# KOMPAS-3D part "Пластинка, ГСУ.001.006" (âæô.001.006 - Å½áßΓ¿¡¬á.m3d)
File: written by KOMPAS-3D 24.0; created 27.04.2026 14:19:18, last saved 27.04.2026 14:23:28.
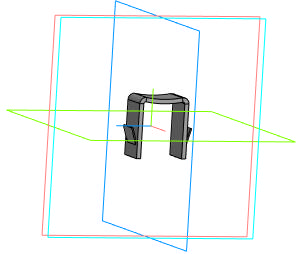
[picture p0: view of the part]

Document properties: Автор: User7; Полное имя файла: C:\Users\User7\Desktop\Двигатель мясорубки\ГСУ.001.006 - Пластинка.m3d

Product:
- Part/product: Пластинка  | designation ГСУ.001.006
    Масса: 0.002129

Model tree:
1. Эскиз:1
2. Обечайка:1
     Расстояние 1 = 7; Радиус сгиба = 0.4; Радиус сгиба = 0.4; Коэффициент = 0.4; Величина сгиба = 10; Радиус сгиба = 25.25; Коэффициент = 0.4; Величина сгиба = 10; Радиус сгиба = 0.4; Коэффициент = 0.4; Величина сгиба = 10; Зазор = 1
3. Смещенная плоскость:1
     Расстояние = 3.5
4. Эскиз:2  (with: Ребро.Обечайка:1)
5. Элемент выдавливания:1
     Толщина стенки 1 = 0.3; Расстояние 1 = 5

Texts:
  ГСУ.001.006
